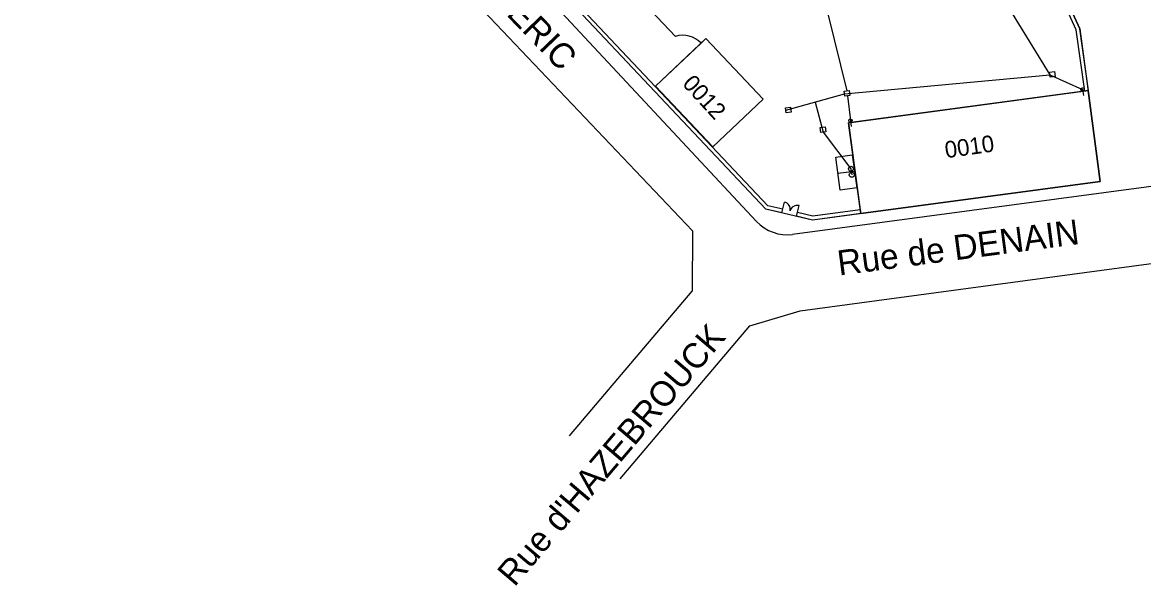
# Model space of a CAD drawing. Extents: x 704421 to 705059, y 7058908 to 7059523.
# Drawn here: x 704446.8 to 704581.3, y 7058907.9 to 7058975.5 of the extents above; entities that cross this region are included whole.
import ezdxf

# ---------------------------------------------------------------- set-up
doc = ezdxf.new("R2010")
doc.units = 0
for name, color, linetype in [('DH_HACHURE-MOTIF', 7, 'Continuous'), ('DH_TEXTE', 7, 'Continuous'), ('GO_MUR_EXTERIEUR', 7, 'Continuous'), ('IMM_LIMITE PHYSIQUE', 7, 'Continuous'), ('R_PLU_CANALISATION_CL_A', 7, 'Continuous'), ('SID_NUMERO_BATI', 7, 'Continuous'), ('SID_POLYLIGNES_BATI', 7, 'Continuous'), ('SID_POLYLIGNES_IMMEUBLE', 7, 'Continuous'), ('SO_EP_EQUIP', 7, 'Continuous'), ('VOIRIE_BORDURE', 7, 'Continuous'), ('VOIRIE_ROUTE', 7, 'Continuous')]:
    doc.layers.add(name, color=color, linetype=linetype)

msp = doc.modelspace()

# ---------------------------------------------------------------- linework, layer by layer
at = {"layer": 'DH_HACHURE-MOTIF'}
for points in [[(704528.21, 7058972.98), (704522.75, 7058967.83), (704529.61, 7058960.55), (704535.66, 7058966.26), (704528.79, 7058973.53), (704528.21, 7058972.98)], [(704547.3, 7058952.98), (704547.36, 7058952.53), (704576.1, 7058956.39), (704574.64, 7058967.29), (704574.19, 7058967.23), (704545.9, 7058963.43), (704547.3, 7058952.98)]]:
    msp.add_lwpolyline(points, dxfattribs=at)
at = {"layer": 'GO_MUR_EXTERIEUR'}
for p, q in [((704522.75, 7058967.83), (704528.79, 7058973.53)), ((704528.79, 7058973.53), (704535.66, 7058966.26)), ((704529.61, 7058960.55), (704522.75, 7058967.83)), ((704545.9, 7058963.43), (704574.64, 7058967.29)), ((704574.64, 7058967.29), (704576.1, 7058956.39)), ((704535.66, 7058966.26), (704529.61, 7058960.55)), ((704547.36, 7058952.53), (704545.9, 7058963.43)), ((704576.1, 7058956.39), (704547.36, 7058952.53))]:
    msp.add_line(p, q, dxfattribs=at)
at = {"layer": 'IMM_LIMITE PHYSIQUE'}
for p, q in [((704472.28, 7059020.59), (704535.98, 7058953.07)), ((704472.61, 7059020.9), (704536.21, 7058953.48)), ((704537.91, 7058952.62), (704535.98, 7058953.07)), ((704538.01, 7058953.06), (704536.21, 7058953.48)), ((704537.91, 7058952.62), (704538.21, 7058953.91)), ((704539.66, 7058952.21), (704539.96, 7058953.5)), ((704547.3, 7058952.98), (704541.61, 7058952.21)), ((704541.59, 7058951.76), (704539.66, 7058952.21)), ((704541.61, 7058952.21), (704539.76, 7058952.65)), ((704547.36, 7058952.53), (704541.59, 7058951.76))]:
    msp.add_line(p, q, dxfattribs=at)
for points in [[(704574.25, 7058967.23), (704573.22, 7058974.58), (704565.32, 7058991.86)], [(704574.7, 7058967.3), (704573.66, 7058974.71), (704565.73, 7058992.05)]]:
    msp.add_lwpolyline(points, dxfattribs=at)
for centre, start, end in [((704538.04, 7058953.05), 346.7916, 78.7098), ((704539.74, 7058952.65), 75.2683, 166.7916)]:
    msp.add_arc(centre, 0.874, start, end, dxfattribs=at)
at = {"layer": 'R_PLU_CANALISATION_CL_A'}
for p, q in [((704543.42, 7058976.51), (704545.68, 7058967.24)), ((704545.43, 7058966.9), (704570.05, 7058969.19)), ((704538.37, 7058964.93), (704545.43, 7058966.9)), ((704545.77, 7058966.65), (704546.13, 7058963.69)), ((704573.99, 7058967.43), (704574.09, 7058966.7)), ((704541.9, 7058965.91), (704542.87, 7058962.31)), ((704546.13, 7058963.69), (704546.2, 7058962.97)), ((704546.61, 7058957.6), (704544.63, 7058957.33))]:
    msp.add_line(p, q, dxfattribs=at)
for points in [[(704561.77, 7058982.71), (704570.05, 7058969.19), (704573.99, 7058967.43)], [(704570.69, 7058968.98), (704570.09, 7058968.89), (704570.01, 7058969.49), (704570.61, 7058969.57), (704570.69, 7058968.98)], [(704546.06, 7058966.69), (704545.47, 7058966.6), (704545.39, 7058967.2), (704545.98, 7058967.28), (704546.06, 7058966.69)], [(704539.01, 7058964.72), (704538.41, 7058964.63), (704538.33, 7058965.23), (704538.92, 7058965.31), (704539.01, 7058964.72)], [(704543.17, 7058962.35), (704542.58, 7058962.27), (704542.49, 7058962.86), (704543.09, 7058962.95), (704543.17, 7058962.35)], [(704542.87, 7058962.31), (704546.19, 7058957.91), (704546.28, 7058957.19)], [(704546.88, 7058955.61), (704544.89, 7058955.35), (704544.36, 7058959.31), (704546.34, 7058959.58), (704546.88, 7058955.61)]]:
    msp.add_lwpolyline(points, dxfattribs=at)
for centre in [(704546.19, 7058957.91), (704546.28, 7058957.19)]:
    msp.add_circle(centre, 0.3, dxfattribs=at)
at = {"layer": 'SID_POLYLIGNES_BATI'}
for p, q in [((704522.75, 7058967.83), (704528.79, 7058973.53)), ((704528.79, 7058973.53), (704535.66, 7058966.26)), ((704529.61, 7058960.55), (704522.75, 7058967.83)), ((704545.9, 7058963.43), (704574.64, 7058967.29)), ((704574.64, 7058967.29), (704576.1, 7058956.39)), ((704535.66, 7058966.26), (704529.61, 7058960.55)), ((704547.36, 7058952.53), (704545.9, 7058963.43)), ((704576.1, 7058956.39), (704547.36, 7058952.53))]:
    msp.add_line(p, q, dxfattribs=at)
at = {"layer": 'SID_POLYLIGNES_IMMEUBLE'}
for p, q in [((704535.98, 7058953.07), (704446.77, 7059047.64)), ((704565.73, 7058992.05), (704573.66, 7058974.71)), ((704573.66, 7058974.71), (704576.1, 7058956.39))]:
    msp.add_line(p, q, dxfattribs=at)
msp.add_lwpolyline([(704576.1, 7058956.39), (704541.59, 7058951.76), (704535.98, 7058953.07)], dxfattribs=at)
at = {"layer": 'SO_EP_EQUIP'}
for centre in [(704573.99, 7058967.43), (704546.13, 7058963.69)]:
    msp.add_circle(centre, 0.2, dxfattribs=at)
at = {"layer": 'VOIRIE_BORDURE'}
msp.add_line((704514.85, 7058984.67), (704525.12, 7058973.78), dxfattribs=at)
msp.add_arc((704526.03, 7058970.92), 3, 43.3308, 107.6513, dxfattribs=at)
at = {"layer": 'VOIRIE_ROUTE'}
for p, q in [((704527.18, 7058950.47), (704470.47, 7059010.13)), ((704482.54, 7059007.66), (704534.87, 7058951.59)), ((704527.18, 7058950.47), (704527.15, 7058943.25)), ((704512.42, 7058925.88), (704527.15, 7058943.25))]:
    msp.add_line(p, q, dxfattribs=at)
for points in [[(704539.19, 7058950.05), (704592.38, 7058957.19)], [(704518.49, 7058920.73), (704534.04, 7058939.07), (704540.1, 7058940.88), (704592.62, 7058947.93)]]:
    msp.add_lwpolyline(points, dxfattribs=at)
msp.add_arc((704538.52, 7058955), 5, 223.0213, 277.6524, dxfattribs=at)

# ---------------------------------------------------------------- texts
at = {"layer": 'DH_TEXTE'}
for s, rotation, p in [('Rue LYDERIC', 313.8024, (704493.48, 7058988.15)), ('Rue de DENAIN', 7.4746, (704544.76, 7058945.1)), ("Rue d'HAZEBROUCK", 49.6268, (704505.81, 7058907.67))]:
    msp.add_text(s, height=3, rotation=rotation, dxfattribs=at).set_placement(p)
at = {"layer": 'SID_NUMERO_BATI'}
for s, rotation, p in [('0012', 312.5129, (704525.86, 7058968.04)), ('0010', 8.0003, (704557.59, 7058959.17))]:
    msp.add_text(s, height=2, rotation=rotation, dxfattribs=at).set_placement(p)

doc.saveas('drawing.dxf')
